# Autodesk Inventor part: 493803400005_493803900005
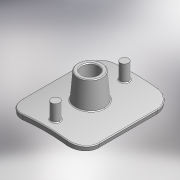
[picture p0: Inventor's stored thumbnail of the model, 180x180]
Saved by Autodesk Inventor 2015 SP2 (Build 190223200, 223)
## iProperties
Created: 2019-01
Part Number: 493803400005_493803900005
Material: PVC-Piping
Description: PLASSON SENSOR ADAPTOR 1/2''
Document SubType Name: Modeling
Designer: KIM
Mass: 92.1368 g
Surface Area: 241.86 cm^2
Volume: 65.812 cm^3
Density: 1.4 g/cm^3
Appearance: Smooth - White
Author: KIM
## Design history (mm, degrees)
derived "493803.ipt"
feature "Solid1::493803.ipt" dims "ScaleForDerivedMember" = 10
tag "TaggingFeature1"
body "Solid1"
other parameters: "d0" = 35 [user parameter], "d1" = 103 [user parameter], "d4" = 85 [user parameter], "d6" = 206 [user parameter], "d8" = 103 [user parameter], "d9" = 0 [user parameter], "d10" = 24.5 [user parameter], "d11" = 24.5 [user parameter], "d13" = 12.36 [user parameter], "d14" = 12.36 [user parameter], "d15" = 18.631 [user parameter], "d16" = 33.5358 [user parameter], "d17" = 27.9465 [user parameter], "d18" = 9.3155 [user parameter], "d20" = 9.3155 [user parameter], "d24" = 18.631 [user parameter], "d25" = 0.93155 [user parameter], "d27" = 0 [user parameter], "Rp" = 18.631 [user parameter], "H_" = 35 [user parameter], "B" = 85 [user parameter], "L" = 103 [user parameter]
